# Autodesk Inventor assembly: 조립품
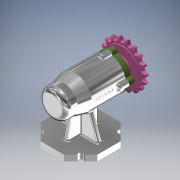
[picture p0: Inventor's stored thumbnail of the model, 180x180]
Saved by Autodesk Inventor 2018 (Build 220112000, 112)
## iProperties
Created: 2021-01
Part Number: 조립품
Material: 일반
Document SubType Name: Assembly
Designer: home
Author: home
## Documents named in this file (11)
- C:\Users\home\Desktop\710106V1035\조립품.iam
- C:\Users\home\Desktop\710106V1035\본체.ipt
- C:\Users\home\Desktop\710106V1035\베어링 6004.ipt
- C:\Users\home\Desktop\710106V1035\커버.ipt
- C:\Users\home\Desktop\710106V1035\볼트 M4.ipt
- C:\Users\home\Desktop\710106V1035\오일 실.ipt
- C:\Users\home\Desktop\710106V1035\어댑터슬리브.ipt
- C:\Users\home\Desktop\710106V1035\베어링 51202.ipt
- C:\Users\home\Desktop\710106V1035\축.ipt
- C:\Users\home\Desktop\710106V1035\키 5 x 5 x 14.ipt
- C:\Users\home\Desktop\710106V1035\스프로킷.ipt
